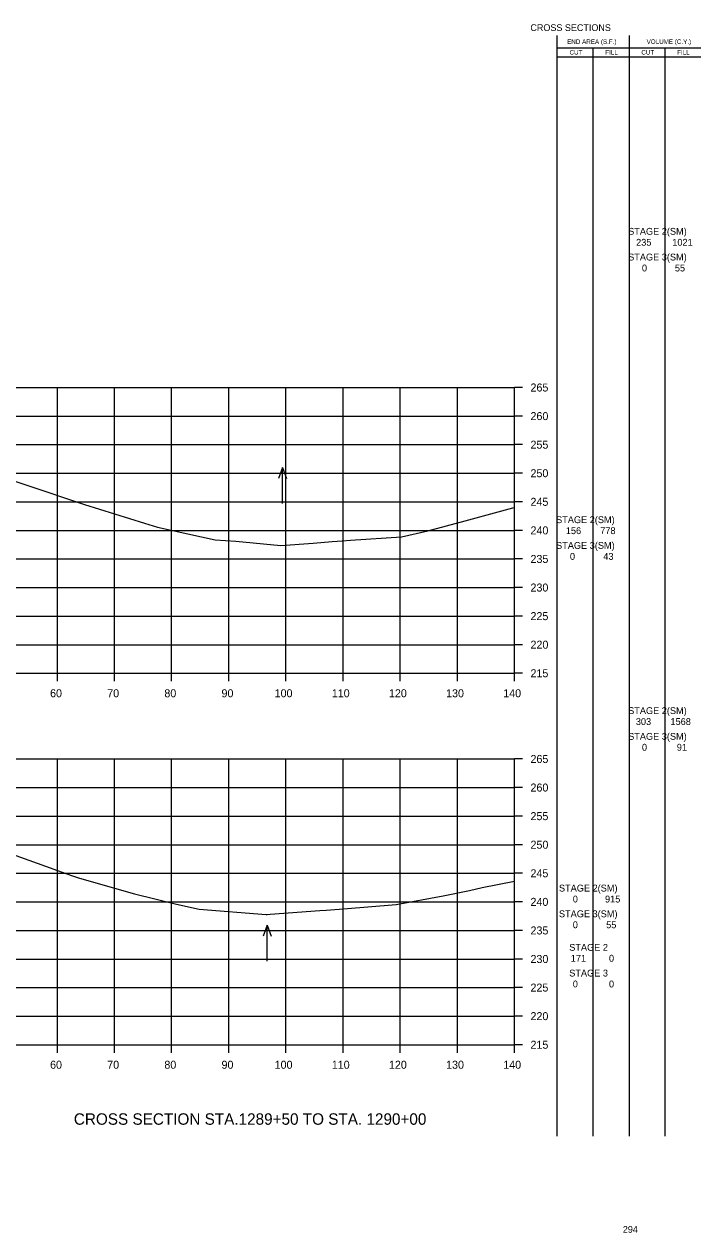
# Model space of a CAD drawing. Extents: x 1342547 to 1344156, y -1532351 to -1517216.
# Drawn here: x 1342757.1 to 1342875.5, y -1521483.8 to -1521272.3 of the extents above; entities that cross this region are included whole.
import ezdxf

# ---------------------------------------------------------------- set-up
doc = ezdxf.new("R2010")
doc.units = 0
for name, color, linetype in [('Level 2', 7, 'Continuous'), ('R_Axis', 7, 'Continuous'), ('R_Axis Annot', 7, 'Continuous'), ('R_Border Notes', 7, 'Continuous'), ('R_Draft', 7, 'Continuous'), ('R_Exist Surface', 7, 'Continuous'), ('R_Grid', 7, 'Continuous'), ('R_Water', 7, 'Continuous')]:
    doc.layers.add(name, color=color, linetype=linetype)

msp = doc.modelspace()

# ---------------------------------------------------------------- linework, layer by layer
at = {"layer": 'Level 2'}
for p, q in [((1342850.33, -1521466.91), (1342850.32, -1521274.31)), ((1342862.99, -1521466.91), (1342862.99, -1521274.31)), ((1342850.32, -1521276.47), (1342863.59, -1521276.47)), ((1342856.66, -1521466.91), (1342856.66, -1521276.47)), ((1342863.59, -1521276.47), (1342875.48, -1521276.47)), ((1342869.23, -1521466.91), (1342869.23, -1521276.47)), ((1342850.32, -1521278.03), (1342863.59, -1521278.03)), ((1342863.59, -1521278.03), (1342875.48, -1521278.03))]:
    msp.add_line(p, q, dxfattribs=at)
at = {"layer": 'R_Axis'}
for p, q in [((1342842.87, -1521385.91), (1342842.87, -1521335.91)), ((1342844.27, -1521335.91), (1342842.87, -1521335.91)), ((1342844.27, -1521340.91), (1342842.87, -1521340.91)), ((1342844.27, -1521345.91), (1342842.87, -1521345.91)), ((1342844.27, -1521350.91), (1342842.87, -1521350.91)), ((1342844.27, -1521355.91), (1342842.87, -1521355.91)), ((1342844.27, -1521360.91), (1342842.87, -1521360.91)), ((1342844.27, -1521365.91), (1342842.87, -1521365.91)), ((1342844.27, -1521370.91), (1342842.87, -1521370.91)), ((1342844.27, -1521375.91), (1342842.87, -1521375.91)), ((1342844.27, -1521380.91), (1342842.87, -1521380.91)), ((1342562.87, -1521385.91), (1342842.87, -1521385.91)), ((1342762.87, -1521387.31), (1342762.87, -1521385.91)), ((1342772.87, -1521387.31), (1342772.87, -1521385.91)), ((1342782.87, -1521387.31), (1342782.87, -1521385.91)), ((1342792.87, -1521387.31), (1342792.87, -1521385.91)), ((1342802.87, -1521387.31), (1342802.87, -1521385.91)), ((1342812.87, -1521387.31), (1342812.87, -1521385.91)), ((1342822.87, -1521387.31), (1342822.87, -1521385.91)), ((1342832.87, -1521387.31), (1342832.87, -1521385.91)), ((1342842.87, -1521387.31), (1342842.87, -1521385.91)), ((1342844.27, -1521385.91), (1342842.87, -1521385.91)), ((1342842.87, -1521450.91), (1342842.87, -1521400.91)), ((1342844.27, -1521400.91), (1342842.87, -1521400.91)), ((1342844.27, -1521405.91), (1342842.87, -1521405.91)), ((1342844.27, -1521410.91), (1342842.87, -1521410.91)), ((1342844.27, -1521415.91), (1342842.87, -1521415.91)), ((1342844.27, -1521420.91), (1342842.87, -1521420.91)), ((1342844.27, -1521425.91), (1342842.87, -1521425.91)), ((1342844.27, -1521430.91), (1342842.87, -1521430.91)), ((1342844.27, -1521435.91), (1342842.87, -1521435.91)), ((1342844.27, -1521440.91), (1342842.87, -1521440.91)), ((1342844.27, -1521445.91), (1342842.87, -1521445.91)), ((1342562.87, -1521450.91), (1342842.87, -1521450.91)), ((1342762.87, -1521452.31), (1342762.87, -1521450.91)), ((1342772.87, -1521452.31), (1342772.87, -1521450.91)), ((1342782.87, -1521452.31), (1342782.87, -1521450.91)), ((1342792.87, -1521452.31), (1342792.87, -1521450.91)), ((1342802.87, -1521452.31), (1342802.87, -1521450.91)), ((1342812.87, -1521452.31), (1342812.87, -1521450.91)), ((1342822.87, -1521452.31), (1342822.87, -1521450.91)), ((1342832.87, -1521452.31), (1342832.87, -1521450.91)), ((1342842.87, -1521452.31), (1342842.87, -1521450.91)), ((1342844.27, -1521450.91), (1342842.87, -1521450.91))]:
    msp.add_line(p, q, dxfattribs=at)
at = {"layer": 'R_Exist Surface'}
for points in [[(1342753.37, -1521351.58), (1342757.54, -1521352.98), (1342767.64, -1521356.39), (1342778.14, -1521359.67), (1342780.38, -1521360.37), (1342785.71, -1521361.54), (1342790.47, -1521362.59), (1342794.11, -1521362.8), (1342801.96, -1521363.54), (1342807.61, -1521363.16), (1342810.96, -1521362.85), (1342812.73, -1521362.74), (1342814.17, -1521362.63), (1342823.07, -1521362.04), (1342827.71, -1521360.99), (1342834.26, -1521359.23), (1342842.58, -1521356.96), (1342842.87, -1521356.89)], [(1342752.82, -1521416.82), (1342764.38, -1521420.96), (1342765.68, -1521421.4), (1342766.73, -1521421.74), (1342776.38, -1521424.49), (1342783.75, -1521426.29), (1342787.69, -1521427.19), (1342799.44, -1521428.11), (1342799.56, -1521428.12), (1342800.09, -1521428.08), (1342808.8, -1521427.43), (1342809.94, -1521427.35), (1342812.95, -1521427.11), (1342822.18, -1521426.4), (1342830.41, -1521424.85), (1342835, -1521423.91), (1342837.23, -1521423.41), (1342842.87, -1521422.3)]]:
    msp.add_lwpolyline(points, dxfattribs=at)
at = {"layer": 'R_Grid'}
for p, q in [((1342562.87, -1521335.91), (1342842.87, -1521335.91)), ((1342762.87, -1521385.91), (1342762.87, -1521335.91)), ((1342772.87, -1521385.91), (1342772.87, -1521335.91)), ((1342782.87, -1521385.91), (1342782.87, -1521335.91)), ((1342792.87, -1521385.91), (1342792.87, -1521335.91)), ((1342802.87, -1521385.91), (1342802.87, -1521335.91)), ((1342812.87, -1521385.91), (1342812.87, -1521335.91)), ((1342822.87, -1521385.91), (1342822.87, -1521335.91)), ((1342832.87, -1521385.91), (1342832.87, -1521335.91)), ((1342842.87, -1521385.91), (1342842.87, -1521335.91)), ((1342562.87, -1521340.91), (1342842.87, -1521340.91)), ((1342562.87, -1521345.91), (1342842.87, -1521345.91)), ((1342562.87, -1521350.91), (1342842.87, -1521350.91)), ((1342562.87, -1521355.91), (1342842.87, -1521355.91)), ((1342562.87, -1521360.91), (1342842.87, -1521360.91)), ((1342562.87, -1521365.91), (1342842.87, -1521365.91)), ((1342562.87, -1521370.91), (1342842.87, -1521370.91)), ((1342562.87, -1521375.91), (1342842.87, -1521375.91)), ((1342562.87, -1521380.91), (1342842.87, -1521380.91)), ((1342562.87, -1521385.91), (1342842.87, -1521385.91)), ((1342562.87, -1521400.91), (1342842.87, -1521400.91)), ((1342762.87, -1521450.91), (1342762.87, -1521400.91)), ((1342772.87, -1521450.91), (1342772.87, -1521400.91)), ((1342782.87, -1521450.91), (1342782.87, -1521400.91)), ((1342792.87, -1521450.91), (1342792.87, -1521400.91)), ((1342802.87, -1521450.91), (1342802.87, -1521400.91)), ((1342812.87, -1521450.91), (1342812.87, -1521400.91)), ((1342822.87, -1521450.91), (1342822.87, -1521400.91)), ((1342832.87, -1521450.91), (1342832.87, -1521400.91)), ((1342842.87, -1521450.91), (1342842.87, -1521400.91)), ((1342562.87, -1521405.91), (1342842.87, -1521405.91)), ((1342562.87, -1521410.91), (1342842.87, -1521410.91)), ((1342562.87, -1521415.91), (1342842.87, -1521415.91)), ((1342562.87, -1521420.91), (1342842.87, -1521420.91)), ((1342562.87, -1521425.91), (1342842.87, -1521425.91)), ((1342562.87, -1521430.91), (1342842.87, -1521430.91)), ((1342562.87, -1521435.91), (1342842.87, -1521435.91)), ((1342562.87, -1521440.91), (1342842.87, -1521440.91)), ((1342562.87, -1521445.91), (1342842.87, -1521445.91)), ((1342562.87, -1521450.91), (1342842.87, -1521450.91))]:
    msp.add_line(p, q, dxfattribs=at)
at = {"layer": 'R_Water'}
for p, q in [((1342802.27, -1521349.9), (1342801.57, -1521351.82)), ((1342802.27, -1521356.18), (1342802.27, -1521349.9)), ((1342802.27, -1521349.9), (1342802.97, -1521351.82)), ((1342799.61, -1521430.01), (1342798.91, -1521431.93)), ((1342799.61, -1521436.29), (1342799.61, -1521430.01)), ((1342799.61, -1521430.01), (1342800.31, -1521431.93))]:
    msp.add_line(p, q, dxfattribs=at)

# ---------------------------------------------------------------- texts
at = {"layer": 'Level 2'}
for s, height, p in [('END AREA (S.F.)', 0.7937, (1342852.08, -1521275.79)), ('VOLUME (C.Y.)', 0.7937, (1342865.99, -1521275.79)), ('CUT', 0.794, (1342852.5, -1521277.65)), ('FILL', 0.794, (1342858.76, -1521277.65)), ('CUT', 0.794, (1342865.07, -1521277.65)), ('FILL', 0.794, (1342871.33, -1521277.65)), (' STAGE 2(SM)  ', 1.2, (1342862.31, -1521309.18)), ('235', 1.2, (1342864.15, -1521311.1)), ('1021', 1.2, (1342870.48, -1521311.1)), (' STAGE 3(SM)  ', 1.2, (1342862.31, -1521313.68)), ('0', 1.2, (1342865.17, -1521315.6)), ('55', 1.2, (1342870.93, -1521315.6)), (' STAGE 2(SM)  ', 1.2, (1342849.7, -1521359.64)), ('156', 1.2, (1342851.85, -1521361.56)), ('778', 1.2, (1342857.87, -1521361.56)), (' STAGE 3(SM)  ', 1.2, (1342849.7, -1521364.14)), ('0', 1.2, (1342852.57, -1521366.06)), ('43', 1.2, (1342858.41, -1521366.06)), (' STAGE 2(SM)  ', 1.2, (1342862.31, -1521393.05)), ('303', 1.2, (1342864.1, -1521394.96)), ('1568', 1.2, (1342870.16, -1521394.96)), (' STAGE 3(SM)  ', 1.2, (1342862.31, -1521397.55)), ('0', 1.2, (1342865.17, -1521399.46)), ('91', 1.2, (1342871.27, -1521399.46)), (' STAGE 2(SM)  ', 1.2, (1342850.2, -1521424.1)), ('0', 1.2, (1342853.07, -1521426.02)), ('915', 1.2, (1342858.71, -1521426.02)), (' STAGE 3(SM)  ', 1.2, (1342850.2, -1521428.6)), ('0', 1.2, (1342853.07, -1521430.52)), ('55', 1.2, (1342858.91, -1521430.52)), (' STAGE 2 ', 1.2, (1342852, -1521434.47)), ('171', 1.2, (1342852.72, -1521436.38)), ('0', 1.2, (1342859.4, -1521436.38)), (' STAGE 3 ', 1.2, (1342852, -1521438.97)), ('0', 1.2, (1342853.07, -1521440.88)), ('0', 1.2, (1342859.4, -1521440.88))]:
    msp.add_text(s, height=height, dxfattribs=at).set_placement(p)
at = {"layer": 'R_Axis Annot'}
for s, p in [('265', (1342845.67, -1521336.61)), ('260', (1342845.67, -1521341.61)), ('255', (1342845.67, -1521346.61)), ('250', (1342845.67, -1521351.61)), ('245', (1342845.67, -1521356.61)), ('240', (1342845.67, -1521361.61)), ('235', (1342845.67, -1521366.61)), ('230', (1342845.67, -1521371.61)), ('225', (1342845.67, -1521376.61)), ('220', (1342845.67, -1521381.61)), ('215', (1342845.67, -1521386.61)), ('60', (1342761.6, -1521390.11)), ('70', (1342771.6, -1521390.11)), ('80', (1342781.6, -1521390.11)), ('90', (1342791.6, -1521390.11)), ('100', (1342800.9, -1521390.11)), ('110', (1342810.9, -1521390.11)), ('120', (1342820.9, -1521390.11)), ('130', (1342830.9, -1521390.11)), ('140', (1342840.9, -1521390.11)), ('265', (1342845.67, -1521401.61)), ('260', (1342845.67, -1521406.61)), ('255', (1342845.67, -1521411.61)), ('250', (1342845.67, -1521416.61)), ('245', (1342845.67, -1521421.61)), ('240', (1342845.67, -1521426.61)), ('235', (1342845.67, -1521431.61)), ('230', (1342845.67, -1521436.61)), ('225', (1342845.67, -1521441.61)), ('220', (1342845.67, -1521446.61)), ('215', (1342845.67, -1521451.61)), ('60', (1342761.6, -1521455.11)), ('70', (1342771.6, -1521455.11)), ('80', (1342781.6, -1521455.11)), ('90', (1342791.6, -1521455.11)), ('100', (1342800.9, -1521455.11)), ('110', (1342810.9, -1521455.11)), ('120', (1342820.9, -1521455.11)), ('130', (1342830.9, -1521455.11)), ('140', (1342840.9, -1521455.11))]:
    msp.add_text(s, height=1.4, dxfattribs=at).set_placement(p)
at = {"layer": 'R_Border Notes'}
for s, height, p in [('CROSS SECTIONS', 1.1775, (1342845.65, -1521273.53)), ('294', 1.178, (1342861.83, -1521483.81))]:
    msp.add_text(s, height=height, dxfattribs=at).set_placement(p)
at = {"layer": 'R_Draft'}
msp.add_text('CROSS SECTION STA.1289+50 TO STA. 1290+00', height=2, dxfattribs=at).set_placement((1342765.76, -1521464.91))

doc.saveas('drawing.dxf')
